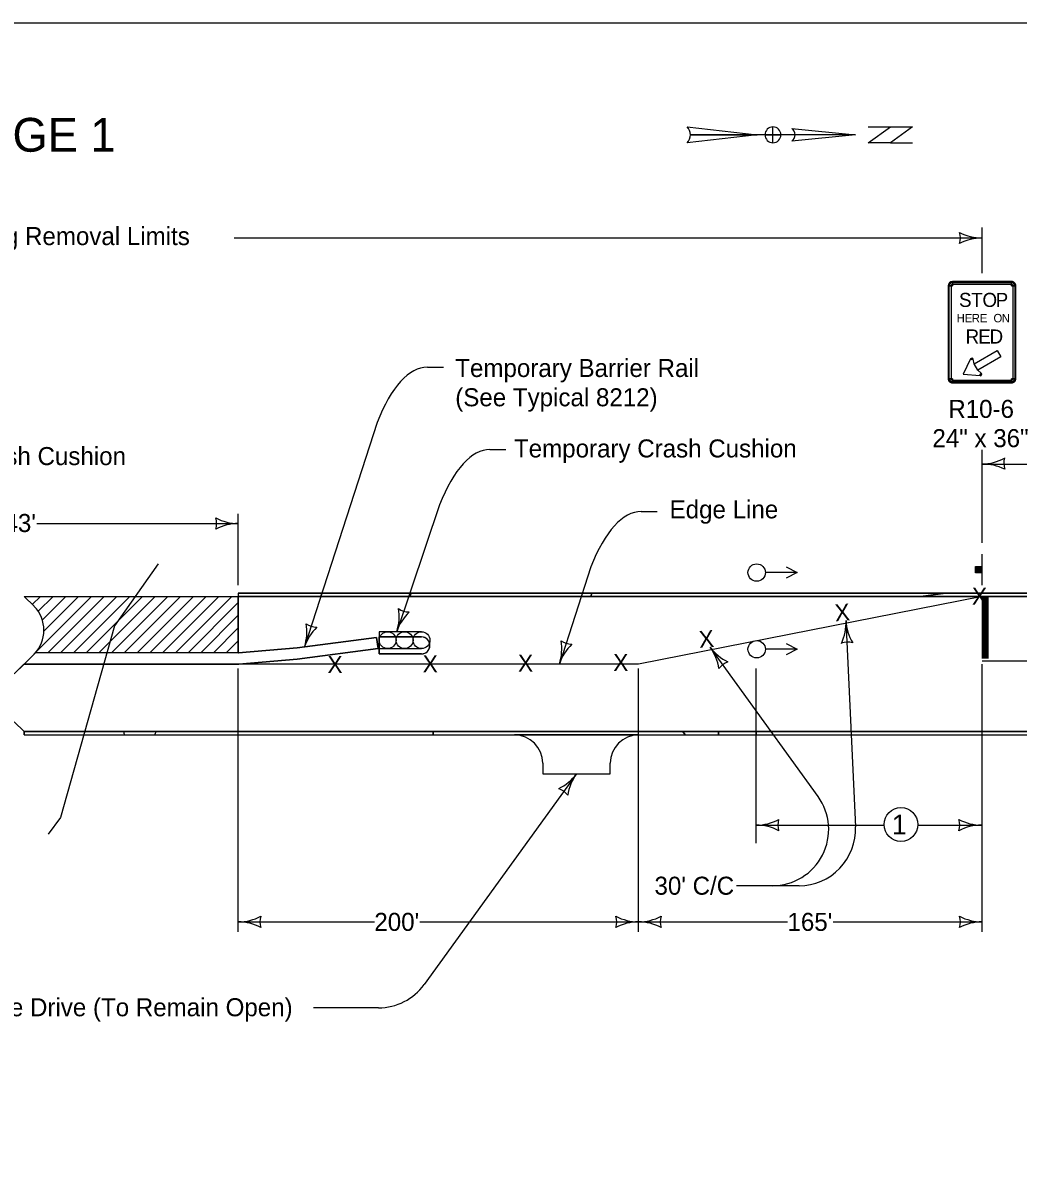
# Model space of a CAD drawing. Extents: x -2134934 to -2127057, y -2139046 to -2137036.
# Drawn here: x -2133366 to -2132482, y -2138047 to -2137036 of the extents above; entities that cross this region are included whole.
import ezdxf

# ---------------------------------------------------------------- set-up
doc = ezdxf.new("R2010")
doc.units = 0
for name, color, linetype in [('Barrier', 7, 'Continuous'), ('BridgeSuperStructureExisting', 7, 'Continuous'), ('Default', 7, 'Continuous'), ('dsnCellsScaleBlock', 7, 'Continuous'), ('DsnShtInsideBorder', 7, 'Continuous'), ('DsnShtPlotIdentification', 7, 'Continuous'), ('DsnShtPlotShape', 7, 'Continuous')]:
    doc.layers.add(name, color=color, linetype=linetype)

msp = doc.modelspace()

# ---------------------------------------------------------------- linework, layer by layer
at = {"layer": 'Barrier'}
for p, q in [((-2132544.4, -2137269.4), (-2132540.7, -2137269.4)), ((-2132543.5, -2137269.4), (-2132541.9, -2137269.4)), ((-2132540.7, -2137269.4), (-2132540.7, -2137265.7)), ((-2132540.7, -2137268.2), (-2132540.7, -2137266.6)), ((-2132488.2, -2137265.7), (-2132488.2, -2137269.4)), ((-2132488.2, -2137266.6), (-2132488.2, -2137268.2)), ((-2132488.2, -2137269.4), (-2132484.4, -2137269.4)), ((-2132486.9, -2137269.4), (-2132485.4, -2137269.4)), ((-2132524.6, -2137334.4), (-2132523.5, -2137335)), ((-2132523.5, -2137335), (-2132522.3, -2137334.7)), ((-2132540.7, -2137351.9), (-2132544.4, -2137351.9)), ((-2132541.9, -2137351.9), (-2132543.5, -2137351.9)), ((-2132540.7, -2137355.7), (-2132540.7, -2137351.9)), ((-2132540.7, -2137354.7), (-2132540.7, -2137353.2)), ((-2132515.1, -2137347), (-2132516, -2137348)), ((-2132516, -2137348), (-2132516, -2137349.2)), ((-2132484.4, -2137351.9), (-2132488.2, -2137351.9)), ((-2132488.2, -2137351.9), (-2132488.2, -2137355.7)), ((-2132488.2, -2137353.2), (-2132488.2, -2137354.7)), ((-2132485.4, -2137351.9), (-2132486.9, -2137351.9))]:
    msp.add_line(p, q, dxfattribs=at)
for points in [[(-2132540.7, -2137355.7), (-2132488.2, -2137355.7), (-2132488.2, -2137351.9), (-2132484.4, -2137351.9), (-2132484.4, -2137269.4), (-2132488.2, -2137269.4), (-2132488.2, -2137265.7), (-2132540.7, -2137265.7), (-2132540.7, -2137269.4), (-2132544.4, -2137269.4), (-2132544.4, -2137351.9), (-2132540.7, -2137351.9), (-2132540.7, -2137355.7)], [(-2132541.9, -2137269.4), (-2132541.9, -2137351.9), (-2132543.5, -2137351.9), (-2132543.5, -2137269.4), (-2132541.9, -2137269.4)], [(-2132488.2, -2137268.2), (-2132540.7, -2137268.2), (-2132540.7, -2137266.6), (-2132488.2, -2137266.6), (-2132488.2, -2137268.2)], [(-2132486.9, -2137351.9), (-2132486.9, -2137269.4), (-2132485.4, -2137269.4), (-2132485.4, -2137351.9), (-2132486.9, -2137351.9)], [(-2132501.1, -2137326.9), (-2132497.8, -2137332.6), (-2132518.1, -2137344.3), (-2132521.4, -2137338.6), (-2132501.1, -2137326.9)], [(-2132531.1, -2137348), (-2132516, -2137349.2), (-2132516, -2137348), (-2132515.1, -2137347), (-2132518.1, -2137344.3), (-2132521.4, -2137338.6), (-2132522.3, -2137334.7), (-2132523.5, -2137335), (-2132524.6, -2137334.4), (-2132531.1, -2137348)], [(-2132540.7, -2137353.2), (-2132488.2, -2137353.2), (-2132488.2, -2137354.7), (-2132540.7, -2137354.7), (-2132540.7, -2137353.2)]]:
    msp.add_lwpolyline(points, close=True, dxfattribs=at)
for centre, radius, start, end in [((-2132540.7, -2137269.4), 3.75, 90.0002, 179.9998), ((-2132540.7, -2137269.4), 2.81, 90.0002, 179.9998), ((-2132540.7, -2137269.4), 1.25, 90.0002, 179.9998), ((-2132488.2, -2137269.4), 3.75, 0, 90.0002), ((-2132488.2, -2137269.4), 2.81, 0, 90.0002), ((-2132488.2, -2137269.4), 1.25, 0, 90.0002), ((-2132523.5, -2137335), 1.25, 12.6223, 152.2756), ((-2132540.7, -2137351.9), 3.75, 179.9998, 270.0001), ((-2132540.7, -2137351.9), 2.81, 179.9998, 270.0001), ((-2132540.7, -2137351.9), 1.25, 179.9998, 270.0001), ((-2132516, -2137348), 1.25, 267.7243, 47.3776), ((-2132488.2, -2137351.9), 3.75, 270.0001, 0.0003), ((-2132488.2, -2137351.9), 2.81, 270.0001, 0.0003), ((-2132488.2, -2137351.9), 1.25, 270.0001, 0.0003)]:
    msp.add_arc(centre, radius, start, end, dxfattribs=at)
at = {"layer": 'BridgeSuperStructureExisting'}
for p, q in [((-2132514.4, -2137258.1), (-2132514.4, -2137217.7)), ((-2133178, -2137227), (-2132514.4, -2137227)), ((-2133006.6, -2137341.6), (-2132992.3, -2137341.6)), ((-2133051.3, -2137390.8), (-2133115.7, -2137590)), ((-2132951.1, -2137414.8), (-2132936.9, -2137414.8)), ((-2132514.4, -2137497.7), (-2132514.4, -2137415.2)), ((-2132514.4, -2137427.7), (-2132459.7, -2137427.7)), ((-2132995.8, -2137463.9), (-2133033.8, -2137576.5)), ((-2133174.4, -2137535.2), (-2133174.4, -2137471.9)), ((-2132816.9, -2137469.9), (-2132802.7, -2137469.9)), ((-2133353.3, -2137480.5), (-2133174.4, -2137480.5)), ((-2132514.4, -2137535.2), (-2132514.4, -2137507.7)), ((-2132861.6, -2137519), (-2132889.5, -2137605.2)), ((-2132706.7, -2137523.7), (-2132678.8, -2137523.7)), ((-2132519.8, -2137524.3), (-2132519.8, -2137518.7)), ((-2132519.5, -2137518.7), (-2132519.5, -2137524.3)), ((-2132519.2, -2137524.3), (-2132519.2, -2137518.7)), ((-2132518.9, -2137518.7), (-2132518.9, -2137524.3)), ((-2132518.7, -2137524.3), (-2132518.7, -2137518.7)), ((-2132518.3, -2137518.7), (-2132518.3, -2137524.3)), ((-2132518, -2137524.3), (-2132518, -2137518.7)), ((-2132517.6, -2137518.7), (-2132517.6, -2137524.3)), ((-2132517.2, -2137524.3), (-2132517.2, -2137518.7)), ((-2132516.9, -2137518.7), (-2132516.9, -2137524.3)), ((-2132516.7, -2137524.3), (-2132516.7, -2137518.7)), ((-2132516.4, -2137518.7), (-2132516.4, -2137524.3)), ((-2132516.1, -2137524.3), (-2132516.1, -2137518.7)), ((-2132515.9, -2137518.7), (-2132515.9, -2137524.3)), ((-2132515.7, -2137524.3), (-2132515.7, -2137518.7)), ((-2132515.4, -2137518.7), (-2132515.4, -2137524.3)), ((-2132515.1, -2137524.3), (-2132515.1, -2137518.7)), ((-2132514.9, -2137518.7), (-2132514.9, -2137524.3)), ((-2133355.7, -2137553.9), (-2133364.4, -2137545.2)), ((-2133357.2, -2137552.4), (-2133350, -2137545.2)), ((-2133353.3, -2137593.7), (-2133304.8, -2137545.2)), ((-2133352, -2137558.4), (-2133338.7, -2137545.2)), ((-2133348.3, -2137566.1), (-2133327.4, -2137545.2)), ((-2133346.9, -2137576), (-2133316.1, -2137545.2)), ((-2133343.4, -2137595.2), (-2133293.4, -2137545.2)), ((-2133332.1, -2137595.2), (-2133282.1, -2137545.2)), ((-2133320.8, -2137595.2), (-2133270.8, -2137545.2)), ((-2133309.5, -2137595.2), (-2133259.5, -2137545.2)), ((-2133298.2, -2137595.2), (-2133248.2, -2137545.2)), ((-2133286.9, -2137595.2), (-2133236.9, -2137545.2)), ((-2133275.6, -2137595.2), (-2133225.6, -2137545.2)), ((-2133264.2, -2137595.2), (-2133214.2, -2137545.2)), ((-2133252.9, -2137595.2), (-2133202.9, -2137545.2)), ((-2133241.6, -2137595.2), (-2133191.6, -2137545.2)), ((-2133230.3, -2137595.2), (-2133180.3, -2137545.2)), ((-2133174.4, -2137595.2), (-2133174.4, -2137545.2)), ((-2131862, -2137545.2), (-2133174.4, -2137545.2)), ((-2133174.4, -2137545.2), (-2133174.4, -2137595.2)), ((-2132514.4, -2137545.2), (-2132819.3, -2137605.2)), ((-2132514.4, -2137545.2), (-2132514.4, -2137600.2)), ((-2132513.4, -2137545.2), (-2132513.4, -2137600.2)), ((-2132512.4, -2137545.2), (-2132512.4, -2137600.2)), ((-2132511.4, -2137545.2), (-2132511.4, -2137600.2)), ((-2132510.4, -2137545.2), (-2132510.4, -2137600.2)), ((-2132509.4, -2137545.2), (-2132509.4, -2137600.2)), ((-2133219, -2137595.2), (-2133174.4, -2137550.6)), ((-2133207.7, -2137595.2), (-2133174.4, -2137561.9)), ((-2133196.4, -2137595.2), (-2133174.4, -2137573.2)), ((-2132635.2, -2137566.6), (-2132626.8, -2137749.7)), ((-2133185.1, -2137595.2), (-2133174.4, -2137584.5)), ((-2133051.7, -2137581.6), (-2133122.2, -2137590.8)), ((-2133122.2, -2137590.8), (-2133051.7, -2137581.6)), ((-2133122.2, -2137590.8), (-2133051.7, -2137581.6)), ((-2133050.4, -2137591.5), (-2133051.7, -2137581.6)), ((-2133051.7, -2137581.6), (-2133050.4, -2137591.5)), ((-2133051.7, -2137581.6), (-2133050.4, -2137591.5)), ((-2133049.4, -2137576.5), (-2133049.4, -2137591.5)), ((-2133011.9, -2137576.5), (-2133049.4, -2137576.5)), ((-2133049.4, -2137596.2), (-2133049.4, -2137581.2)), ((-2133049.4, -2137581.2), (-2133011.9, -2137581.2)), ((-2133373.2, -2137613.9), (-2133355.7, -2137596.4)), ((-2133355.7, -2137596.4), (-2133364.4, -2137605.2)), ((-2133174.3, -2137595.2), (-2133354.4, -2137595.2)), ((-2133174.3, -2137595.2), (-2133354.4, -2137595.2)), ((-2133174.4, -2137595.2), (-2133122.2, -2137590.8)), ((-2133122.2, -2137590.8), (-2133174.3, -2137595.2)), ((-2133174.3, -2137595.2), (-2133122.2, -2137590.8)), ((-2133122.3, -2137600.8), (-2133050.4, -2137591.5)), ((-2133050.4, -2137591.5), (-2133122.3, -2137600.8)), ((-2133050.4, -2137591.5), (-2133122.3, -2137600.8)), ((-2133049.4, -2137591.5), (-2133011.9, -2137591.5)), ((-2133011.9, -2137596.2), (-2133049.4, -2137596.2)), ((-2132660, -2137722.7), (-2132755.8, -2137590.2)), ((-2132706.7, -2137591.7), (-2132678.8, -2137591.7)), ((-2133364.4, -2137605.2), (-2133173.9, -2137605.2)), ((-2133173.9, -2137605.2), (-2133364.4, -2137605.2)), ((-2133173.9, -2137605.2), (-2133364.4, -2137605.2)), ((-2133173.9, -2137605.2), (-2133122.3, -2137600.8)), ((-2133122.3, -2137600.8), (-2133173.9, -2137605.2)), ((-2133122.3, -2137600.8), (-2133173.9, -2137605.2)), ((-2132819.3, -2137605.2), (-2133173.9, -2137605.2)), ((-2132514.4, -2137842.8), (-2132514.4, -2137605.2)), ((-2133174.4, -2137842.8), (-2133174.4, -2137609.3)), ((-2132819.3, -2137842.8), (-2132819.3, -2137609.3)), ((-2132714.9, -2137764.1), (-2132714.9, -2137609.3)), ((-2133364.4, -2137665.2), (-2133373.2, -2137656.4)), ((-2133373.2, -2137656.4), (-2133364.4, -2137665.2)), ((-2133364.4, -2137665.2), (-2131862, -2137665.2)), ((-2132819.3, -2137668.2), (-2132929.3, -2137668.2)), ((-2132874.3, -2137702.6), (-2133009.5, -2137889.7)), ((-2132714.9, -2137748.2), (-2132601.4, -2137748.2)), ((-2132571.4, -2137748.2), (-2132514.9, -2137748.2)), ((-2132676.8, -2137802), (-2132732.2, -2137802)), ((-2133174.4, -2137834.1), (-2133053.7, -2137834.1)), ((-2133013.2, -2137834.1), (-2132819.3, -2137834.1)), ((-2132819.3, -2137834.1), (-2132687.1, -2137834.1)), ((-2132646.6, -2137834.1), (-2132514.4, -2137834.1)), ((-2133050, -2137910.4), (-2133107.8, -2137910.4))]:
    msp.add_line(p, q, dxfattribs=at)
for points in [[(-2133245.5, -2137516.3), (-2133284.2, -2137571.3), (-2133332.1, -2137741.4), (-2133343.1, -2137756.3)], [(-2132688.4, -2137518.9), (-2132678.4, -2137523.9), (-2132688.4, -2137528.9)], [(-2133364.4, -2137545.2), (-2133174.4, -2137545.2)], [(-2133354.4, -2137595.2), (-2133354.5, -2137595.1)], [(-2132688.4, -2137586.9), (-2132678.4, -2137591.9), (-2132688.4, -2137596.9)], [(-2133364.4, -2137605.2), (-2133364.4, -2137605.2), (-2133373.2, -2137613.9)], [(-2132904.3, -2137693.2), (-2132904.3, -2137702.6), (-2132844.3, -2137702.6), (-2132844.3, -2137693.2)]]:
    msp.add_lwpolyline(points, dxfattribs=at)
msp.add_lwpolyline([(-2132514.5, -2137518.7), (-2132514.5, -2137524.3), (-2132520.2, -2137524.3), (-2132520.2, -2137518.7)], close=True, dxfattribs=at)
for centre, radius in [((-2132714.4, -2137524), 7.74), ((-2133041.9, -2137584), 7.5), ((-2133041.9, -2137584), 7.5), ((-2133026.9, -2137584), 7.5), ((-2133026.9, -2137584), 7.5), ((-2133011.9, -2137584), 7.5), ((-2133011.9, -2137584), 7.5), ((-2132714.4, -2137592.1), 7.74), ((-2132586.4, -2137747.7), 15)]:
    msp.add_circle(centre, radius, dxfattribs=at)
for centre, radius, start, end in [((-2132515.2, -2137385.2), 42.5, 271.0176, 299.0725), ((-2132478.8, -2137427), 16.4, 163.2666, 198.7334), ((-2132513.7, -2137470.2), 42.5, 62.9275, 90.9824), ((-2133210.1, -2137480.5), 16.4, 342.2666, 17.7333), ((-2133174.4, -2137438), 42.5, 241.9275, 270), ((-2133174.4, -2137523), 42.5, 90, 118.0725), ((-2133376.9, -2137575.2), 30, 315, 45), ((-2133011.9, -2137588.7), 7.5, 269.9996, 90), ((-2133376.9, -2137575.2), 30, 315, 318.2713), ((-2132929.3, -2137693.2), 25, 0, 90), ((-2132819.3, -2137693.2), 25, 90, 180), ((-2132700.5, -2137752), 50, 270, 35.862), ((-2132714.9, -2137705.7), 42.5, 270, 298.0725), ((-2132714.9, -2137790.7), 42.5, 61.9275, 90), ((-2132679.3, -2137748.2), 16.4, 162.2666, 197.7334), ((-2132550.6, -2137748.2), 16.4, 342.2666, 17.7333), ((-2132514.9, -2137705.7), 42.5, 241.9275, 270), ((-2132514.9, -2137790.7), 42.5, 90, 118.0725), ((-2132676.8, -2137752), 50, 270, 2.6154), ((-2133050, -2137860.4), 50, 270, 324.138)]:
    msp.add_arc(centre, radius, start, end, dxfattribs=at)
for centre in [(-2133006.6, -2137554.6), (-2132951.1, -2137627.7), (-2132816.9, -2137682.8)]:
    msp.add_ellipse(centre, major_axis=(0, 212.9), ratio=0.328743, start_param=0, end_param=0.693162, dxfattribs=at)
at = {"layer": 'Default'}
msp.add_lwpolyline([(-2134934.4, -2137035.9), (-2131799.4, -2137035.9), (-2131799.4, -2139045.9), (-2134934.4, -2139045.9)], close=True, dxfattribs=at)
at = {"layer": 'dsnCellsScaleBlock'}
for p, q in [((-2132776.1, -2137128.4), (-2132714.1, -2137135.4)), ((-2132683.1, -2137129.8), (-2132683.1, -2137129.8)), ((-2132682.6, -2137130), (-2132681.4, -2137131.1)), ((-2132626.8, -2137135.4), (-2132773.3, -2137135.4)), ((-2132707.1, -2137135.4), (-2132707.1, -2137135.4)), ((-2132626.8, -2137135.4), (-2132683.1, -2137141.1))]:
    msp.add_line(p, q, dxfattribs=at)
for points in [[(-2132707.1, -2137135.4), (-2132700, -2137135.4), (-2132700, -2137128.4)], [(-2132683.1, -2137129.8), (-2132626.8, -2137135.4), (-2132680.3, -2137135.4)], [(-2132615.5, -2137128.4), (-2132576.1, -2137128.4), (-2132595.8, -2137142.5), (-2132576.1, -2137142.5)], [(-2132773.3, -2137135.4), (-2132714.1, -2137135.4), (-2132776.1, -2137142.5)], [(-2132700, -2137142.5), (-2132700, -2137135.4), (-2132693, -2137135.4)]]:
    msp.add_lwpolyline(points, dxfattribs=at)
msp.add_lwpolyline([(-2132615.5, -2137142.5), (-2132595.8, -2137128.4), (-2132576.1, -2137128.4), (-2132595.8, -2137142.5)], close=True, dxfattribs=at)
for centre, radius, start, end in [((-2132783.5, -2137135.4), 10.2, 359.9894, 43.619), ((-2132700, -2137135.4), 7.04, 90, 180), ((-2132700, -2137135.4), 7.04, 360, 90), ((-2132687.4, -2137135.4), 7.04, 0.0204, 53.1257), ((-2132783.5, -2137135.4), 10.2, 316.4021, 0.0006), ((-2132700, -2137135.4), 7.04, 180, 270), ((-2132700, -2137135.4), 7.04, 270, 360), ((-2132687.4, -2137135.4), 7.04, 306.8481, 0.0218)]:
    msp.add_arc(centre, radius, start, end, dxfattribs=at)
at = {"layer": 'DsnShtInsideBorder'}
for p, q in [((-2133011.9, -2137581.2), (-2133049.4, -2137581.2)), ((-2133049.4, -2137581.2), (-2133049.4, -2137596.2)), ((-2133049.4, -2137596.2), (-2133011.9, -2137596.2))]:
    msp.add_line(p, q, dxfattribs=at)
msp.add_arc((-2133011.9, -2137588.7), 7.5, 270.0024, 89.9972, dxfattribs=at)
at = {"layer": 'DsnShtPlotIdentification'}
for p, q in [((-2133174.4, -2137542.2), (-2133174.4, -2137545.2)), ((-2133174.4, -2137542.2), (-2133174.4, -2137545.2)), ((-2133100.2, -2137542.2), (-2133174.4, -2137542.2)), ((-2133174.4, -2137545.2), (-2133173.7, -2137545.2)), ((-2133173.7, -2137545.2), (-2133101.2, -2137545.2)), ((-2133100.2, -2137542.2), (-2133101.2, -2137545.2)), ((-2133101.2, -2137545.2), (-2133100.2, -2137542.2)), ((-2133101.2, -2137545.2), (-2133022.1, -2137545.2)), ((-2133021.1, -2137542.2), (-2133100.2, -2137542.2)), ((-2133021.1, -2137542.2), (-2133022.1, -2137545.2)), ((-2133022.1, -2137545.2), (-2133021.1, -2137542.2)), ((-2133022.1, -2137545.2), (-2132861.6, -2137545.2)), ((-2132860.7, -2137542.2), (-2133021.1, -2137542.2)), ((-2132860.7, -2137542.2), (-2132861.6, -2137545.2)), ((-2132861.6, -2137545.2), (-2132860.7, -2137542.2)), ((-2132861.6, -2137545.2), (-2132568.7, -2137545.2)), ((-2132547, -2137542.2), (-2132860.7, -2137542.2)), ((-2132547, -2137542.2), (-2132568.7, -2137545.2)), ((-2132568.7, -2137545.2), (-2132547, -2137542.2)), ((-2132568.7, -2137545.2), (-2132514.4, -2137545.2)), ((-2131862, -2137542.2), (-2132547, -2137542.2)), ((-2132509.4, -2137545.2), (-2131862, -2137545.2)), ((-2131861.9, -2137602.7), (-2132514.4, -2137602.7)), ((-2133364.4, -2137668.2), (-2133364.4, -2137665.2)), ((-2133364.4, -2137665.2), (-2131862, -2137665.2)), ((-2133364.4, -2137665.2), (-2131862, -2137665.2)), ((-2133276.3, -2137665.2), (-2133364.4, -2137665.2)), ((-2133364.4, -2137665.2), (-2133364.4, -2137668.2)), ((-2133247.5, -2137665.2), (-2133276.3, -2137665.2)), ((-2133001.5, -2137665.2), (-2133247.5, -2137665.2)), ((-2133001.5, -2137668.2), (-2133001.5, -2137665.2)), ((-2132780.1, -2137665.2), (-2133001.5, -2137665.2)), ((-2133001.5, -2137665.2), (-2133001.5, -2137668.2)), ((-2132778, -2137668.2), (-2132780.1, -2137665.2)), ((-2132780.1, -2137665.2), (-2132778, -2137668.2)), ((-2132748.3, -2137665.2), (-2132780.1, -2137665.2)), ((-2132748.2, -2137668.2), (-2132748.3, -2137665.2)), ((-2132714.9, -2137665.2), (-2132748.3, -2137665.2)), ((-2132748.3, -2137665.2), (-2132748.2, -2137668.2)), ((-2132714.9, -2137668.2), (-2132714.9, -2137665.2)), ((-2132441.1, -2137665.2), (-2132714.9, -2137665.2)), ((-2132714.9, -2137665.2), (-2132714.9, -2137668.2)), ((-2133364.4, -2137668.2), (-2131862, -2137668.2)), ((-2133364.4, -2137668.2), (-2133275.4, -2137668.2)), ((-2133275.4, -2137668.2), (-2133248.5, -2137668.2)), ((-2133248.5, -2137668.2), (-2133001.5, -2137668.2)), ((-2133001.5, -2137668.2), (-2132778, -2137668.2)), ((-2132778, -2137668.2), (-2132748.2, -2137668.2)), ((-2132748.2, -2137668.2), (-2132714.9, -2137668.2)), ((-2132714.9, -2137668.2), (-2132442.1, -2137668.2))]:
    msp.add_line(p, q, dxfattribs=at)
for points in [[(-2133174.4, -2137542.2), (-2131862, -2137542.2)], [(-2133174.4, -2137545.2), (-2131862, -2137545.2)], [(-2133173.7, -2137545.2), (-2131861.3, -2137545.2)], [(-2132514.4, -2137545.2), (-2132513.4, -2137545.2), (-2132512.4, -2137545.2)], [(-2132512.4, -2137545.2), (-2132511.4, -2137545.2), (-2132510.4, -2137545.2), (-2132509.4, -2137545.2)]]:
    msp.add_lwpolyline(points, dxfattribs=at)
for start, end in [(191.3299, 203.618), (191.3299, 203.618), (336.382, 348.6701), (336.382, 348.6701)]:
    msp.add_arc((-2133261.9, -2137662.3), 14.7, start, end, dxfattribs=at)
at = {"layer": 'DsnShtPlotShape'}
for centre, radius, start, end in [((-2132550.1, -2137227), 16.4, 342.2666, 17.7333), ((-2132514.4, -2137184.5), 42.5, 241.9275, 270), ((-2132514.4, -2137269.5), 42.5, 90, 118.0725), ((-2133074.2, -2137563.4), 42.5, 342.0849, 10.1574), ((-2133022.8, -2137542.6), 16.4, 234.3516, 269.8183), ((-2132993.3, -2137589.6), 42.5, 134.0124, 162.0849), ((-2133156.1, -2137576.9), 42.5, 342.0849, 10.1574), ((-2133075.2, -2137603.1), 42.5, 134.0124, 162.0849), ((-2133104.7, -2137556.1), 16.4, 234.3516, 269.8183), ((-2132677.6, -2137568.6), 42.5, 334.5429, 2.6154), ((-2132592.7, -2137564.7), 42.5, 182.6154, 210.6879), ((-2132929.9, -2137592.1), 42.5, 342.0849, 10.1574), ((-2132878.5, -2137571.2), 16.4, 234.3516, 269.8183), ((-2132633.6, -2137602.2), 16.4, 74.8821, 110.3488), ((-2132849, -2137618.2), 42.5, 134.0124, 162.0849), ((-2132721.5, -2137565), 42.5, 216.299, 244.3715), ((-2132790, -2137615.4), 42.5, 8.2265, 36.299), ((-2132734.7, -2137618.9), 16.4, 108.5657, 144.0324), ((-2132908.5, -2137677.5), 42.5, 295.6285, 323.701), ((-2132840, -2137727.8), 42.5, 143.701, 171.7735), ((-2132895.4, -2137731.4), 16.4, 35.9676, 71.4343), ((-2133174.4, -2137791.6), 42.5, 270, 298.0725), ((-2133138.8, -2137834.1), 16.4, 162.2666, 197.7334), ((-2132854.9, -2137834.1), 16.4, 342.2666, 17.7333), ((-2132819.3, -2137791.6), 42.5, 241.9275, 270), ((-2132819.3, -2137791.6), 42.5, 270, 298.0725), ((-2132783.6, -2137834.1), 16.4, 162.2666, 197.7334), ((-2132550.1, -2137834.1), 16.4, 342.2666, 17.7333), ((-2132514.4, -2137791.6), 42.5, 241.9275, 270), ((-2133174.4, -2137876.6), 42.5, 61.9275, 90), ((-2132819.3, -2137876.6), 42.5, 90, 118.0725), ((-2132819.3, -2137876.6), 42.5, 61.9275, 90), ((-2132514.4, -2137876.6), 42.5, 90, 118.0725)]:
    msp.add_arc(centre, radius, start, end, dxfattribs=at)

# ---------------------------------------------------------------- texts
at = {"layer": 'Barrier'}
for s, height, p in [('STAGE 1', 30, (-2133452.8, -2137150.4)), ('S', 12.5, (-2132534.9, -2137288.2)), ('T', 12.5, (-2132524.1, -2137288.2)), ('O', 12.5, (-2132514.1, -2137288.2)), ('P', 12.5, (-2132502.4, -2137288.2)), ('H', 7.5, (-2132537, -2137301.9)), ('E', 7.5, (-2132529.8, -2137301.9)), ('R', 7.5, (-2132523.6, -2137301.9)), ('E', 7.5, (-2132516.4, -2137301.9)), ('O', 7.5, (-2132504.3, -2137301.9)), ('N', 7.5, (-2132497, -2137301.9)), ('R', 12.5, (-2132529.1, -2137320.7)), ('E', 12.5, (-2132517.8, -2137320.7)), ('D', 12.5, (-2132507.8, -2137320.7)), ('R10-6', 16, (-2132544.4, -2137386.7)), ('24" x 36"', 16, (-2132558.5, -2137412.7))]:
    msp.add_text(s, height=height, dxfattribs=at).set_placement(p)
at = {"layer": 'BridgeSuperStructureExisting'}
for s, height, p in [('Pavement Marking Removal Limits', 16, (-2133548, -2137233.3)), ('Temporary Barrier Rail', 16, (-2132981.9, -2137350.4)), ('(See Typical 8212)', 16, (-2132981.9, -2137376.4)), ('Temporary Crash Cushion', 16, (-2133525, -2137428.6)), ('Temporary Crash Cushion', 16, (-2132929.8, -2137421.8)), ('Edge Line', 16, (-2132791.7, -2137475.9)), ("343'", 16, (-2133393.8, -2137488)), ('X', 15, (-2132523.4, -2137552.5)), ('X', 15, (-2132841.7, -2137611.4)), ('X', 15, (-2133095.3, -2137613.2)), ('X', 15, (-2133010.8, -2137612.6)), ('X', 15, (-2132926.2, -2137612)), ('1', 17.5, (-2132594.4, -2137756.5)), ("30' C/C", 16, (-2132805.1, -2137810)), ("200'", 16, (-2133053.7, -2137842.1)), ("165'", 16, (-2132687.1, -2137842.1)), ('Private Drive (To Remain Open)', 16, (-2133431.8, -2137917.9))]:
    msp.add_text(s, height=height, dxfattribs=at).set_placement(p)
for p in [(-2132644.6, -2137567.3), (-2132765.2, -2137590.9)]:
    msp.add_text('X', height=15, rotation=4.123, dxfattribs=at).set_placement(p)

doc.saveas('drawing.dxf')
